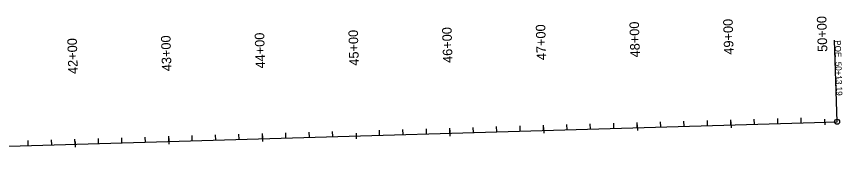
# Model space of a CAD drawing. Extents: x 21446797 to 21450291, y 8416521 to 8417382.
# Drawn here: x 21449409 to 21450291, y 8417019 to 8417164 of the extents above; entities that cross this region are included whole.
import ezdxf

# ---------------------------------------------------------------- set-up
doc = ezdxf.new("R2010")
doc.units = 0
for name, color, linetype in [('Default', 7, 'Continuous'), ('Terrain', 7, 'Continuous'), ('TextAlignment', 7, 'Continuous'), ('TextAlignmentLrg', 7, 'Continuous'), ('TextAlignmentSml', 7, 'Continuous')]:
    doc.layers.add(name, color=color, linetype=linetype)

msp = doc.modelspace()

# ---------------------------------------------------------------- linework, layer by layer
at = {"layer": 'Default'}
msp.add_line((21449171.77, 8417018.52), (21450284.85, 8417051.39), dxfattribs=at)
at = {"layer": 'Terrain'}
msp.add_line((21449171.77, 8417018.52), (21450284.85, 8417051.39), dxfattribs=at)
at = {"layer": 'TextAlignment'}
msp.add_line((21450284.85, 8417051.39), (21450282.28, 8417138.35), dxfattribs=at)
msp.add_circle((21450284.85, 8417051.39), 2.67, dxfattribs=at)
at = {"layer": 'TextAlignmentLrg'}
for p, q in [((21449971.79, 8417042.14), (21449971.63, 8417047.6)), ((21450071.75, 8417045.1), (21450071.59, 8417050.55)), ((21450171.71, 8417048.05), (21450171.55, 8417053.51)), ((21450271.57, 8417054.06), (21450271.75, 8417047.94)), ((21449671.93, 8417033.29), (21449671.76, 8417038.75)), ((21449771.79, 8417039.3), (21449771.97, 8417033.18)), ((21449871.84, 8417039.19), (21449871.68, 8417044.65)), ((21449472.01, 8417027.38), (21449471.85, 8417032.84)), ((21449571.97, 8417030.34), (21449571.81, 8417035.79))]:
    msp.add_line(p, q, dxfattribs=at)
at = {"layer": 'TextAlignmentSml'}
for p, q in [((21450221.69, 8417049.53), (21450221.52, 8417054.98)), ((21450246.67, 8417050.26), (21450246.51, 8417055.72)), ((21449921.82, 8417040.67), (21449921.65, 8417046.13)), ((21449946.81, 8417041.41), (21449946.64, 8417046.86)), ((21449996.78, 8417042.88), (21449996.62, 8417048.34)), ((21450021.77, 8417043.62), (21450021.61, 8417049.08)), ((21450046.76, 8417044.36), (21450046.6, 8417049.82)), ((21450071.66, 8417048.16), (21450071.84, 8417042.04)), ((21450096.74, 8417045.84), (21450096.58, 8417051.29)), ((21450121.73, 8417046.57), (21450121.57, 8417052.03)), ((21450146.72, 8417047.31), (21450146.56, 8417052.77)), ((21450171.62, 8417051.11), (21450171.8, 8417044.99)), ((21450196.7, 8417048.79), (21450196.54, 8417054.24)), ((21450271.57, 8417054.06), (21450271.75, 8417047.94)), ((21449621.95, 8417031.81), (21449621.79, 8417037.27)), ((21449646.94, 8417032.55), (21449646.77, 8417038.01)), ((21449696.91, 8417034.03), (21449696.75, 8417039.48)), ((21449721.9, 8417034.76), (21449721.74, 8417040.22)), ((21449746.89, 8417035.5), (21449746.73, 8417040.96)), ((21449771.79, 8417039.3), (21449771.97, 8417033.18)), ((21449796.87, 8417036.98), (21449796.71, 8417042.44)), ((21449821.86, 8417037.72), (21449821.7, 8417043.17)), ((21449846.85, 8417038.45), (21449846.69, 8417043.91)), ((21449871.75, 8417042.25), (21449871.93, 8417036.13)), ((21449896.83, 8417039.93), (21449896.67, 8417045.39)), ((21449971.7, 8417045.2), (21449971.88, 8417039.09)), ((21449422.03, 8417025.91), (21449421.87, 8417031.36)), ((21449447.02, 8417026.65), (21449446.86, 8417032.1)), ((21449471.92, 8417030.44), (21449472.1, 8417024.32)), ((21449497, 8417028.12), (21449496.84, 8417033.58)), ((21449521.99, 8417028.86), (21449521.83, 8417034.32)), ((21449546.98, 8417029.6), (21449546.82, 8417035.06)), ((21449571.88, 8417033.39), (21449572.06, 8417027.28)), ((21449596.96, 8417031.07), (21449596.8, 8417036.53)), ((21449671.83, 8417036.35), (21449672.02, 8417030.23))]:
    msp.add_line(p, q, dxfattribs=at)

# ---------------------------------------------------------------- texts
at = {"layer": 'TextAlignment'}
for s, p in [('POE ', (21450282.38, 8417138.36)), ('50+13.19', (21450283.06, 8417115.46))]:
    msp.add_text(s, height=6.48, rotation=271.69178, dxfattribs=at).set_placement(p)
at = {"layer": 'TextAlignmentLrg'}
for s, p in [('50+00', (21450274.55, 8417126.12)), ('45+00', (21449774.77, 8417111.36))]:
    msp.add_text(s, height=10.2, rotation=91.69178, dxfattribs=at).set_placement(p)
at = {"layer": 'TextAlignmentSml'}
for s, p in [('49+00', (21450174.59, 8417123.17)), ('50+00', (21450274.55, 8417126.12)), ('46+00', (21449874.72, 8417114.31)), ('47+00', (21449974.68, 8417117.26)), ('48+00', (21450074.63, 8417120.21)), ('43+00', (21449574.85, 8417105.45)), ('44+00', (21449674.81, 8417108.41)), ('45+00', (21449774.77, 8417111.36)), ('42+00', (21449474.9, 8417102.5))]:
    msp.add_text(s, height=10.2, rotation=91.69178, dxfattribs=at).set_placement(p)

doc.saveas('drawing.dxf')
